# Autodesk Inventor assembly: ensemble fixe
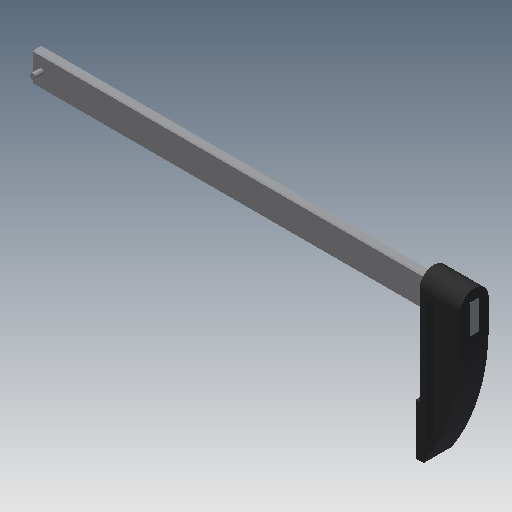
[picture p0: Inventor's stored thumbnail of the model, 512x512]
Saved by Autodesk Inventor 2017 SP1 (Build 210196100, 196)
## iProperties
Created: 2015-12
Part Number: ensemble fixe
Material: Générique
Document SubType Name: Assembly
Designer: Papa
Author: Papa
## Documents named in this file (4)
- H:\Consmec\1si\Cours\Leçon 04 - Schématisation\04-02-TD Schematisation\04-02-04-TD4Serre Joint\04-02-04-02-SerreJoint 3D\ensemble fixe.iam
- H:\Consmec\1si\Cours\Leçon 04 - Schématisation\04-02-TD Schematisation\04-02-04-TD4Serre Joint\04-02-04-02-SerreJoint 3D\01-Guide.ipt
- H:\Consmec\1si\Cours\Leçon 04 - Schématisation\04-02-TD Schematisation\04-02-04-TD4Serre Joint\04-02-04-02-SerreJoint 3D\02-Pion.ipt
- H:\Consmec\1si\Cours\Leçon 04 - Schématisation\04-02-TD Schematisation\04-02-04-TD4Serre Joint\04-02-04-02-SerreJoint 3D\03-Mors_fixe.ipt
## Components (3 placed, 3 different names)
1. 01-Guide:1 — Affleurement:1, Placage:1, Placage:2, Logement:1
2. 02-Pion:1 — Logement:1
3. 03-Mors_fixe:1 — Affleurement:1, Placage:1, Placage:2
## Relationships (4: Mate 2, Flush 1, Insert 1)
- Affleurement:1 [Flush]: 01-Guide:1 ↔ 03-Mors_fixe:1
- Placage:1 [Mate]: 01-Guide:1 ↔ 03-Mors_fixe:1
- Placage:2 [Mate]: 01-Guide:1 ↔ 03-Mors_fixe:1
- Logement:1 [Insert]: 01-Guide:1 ↔ 02-Pion:1
